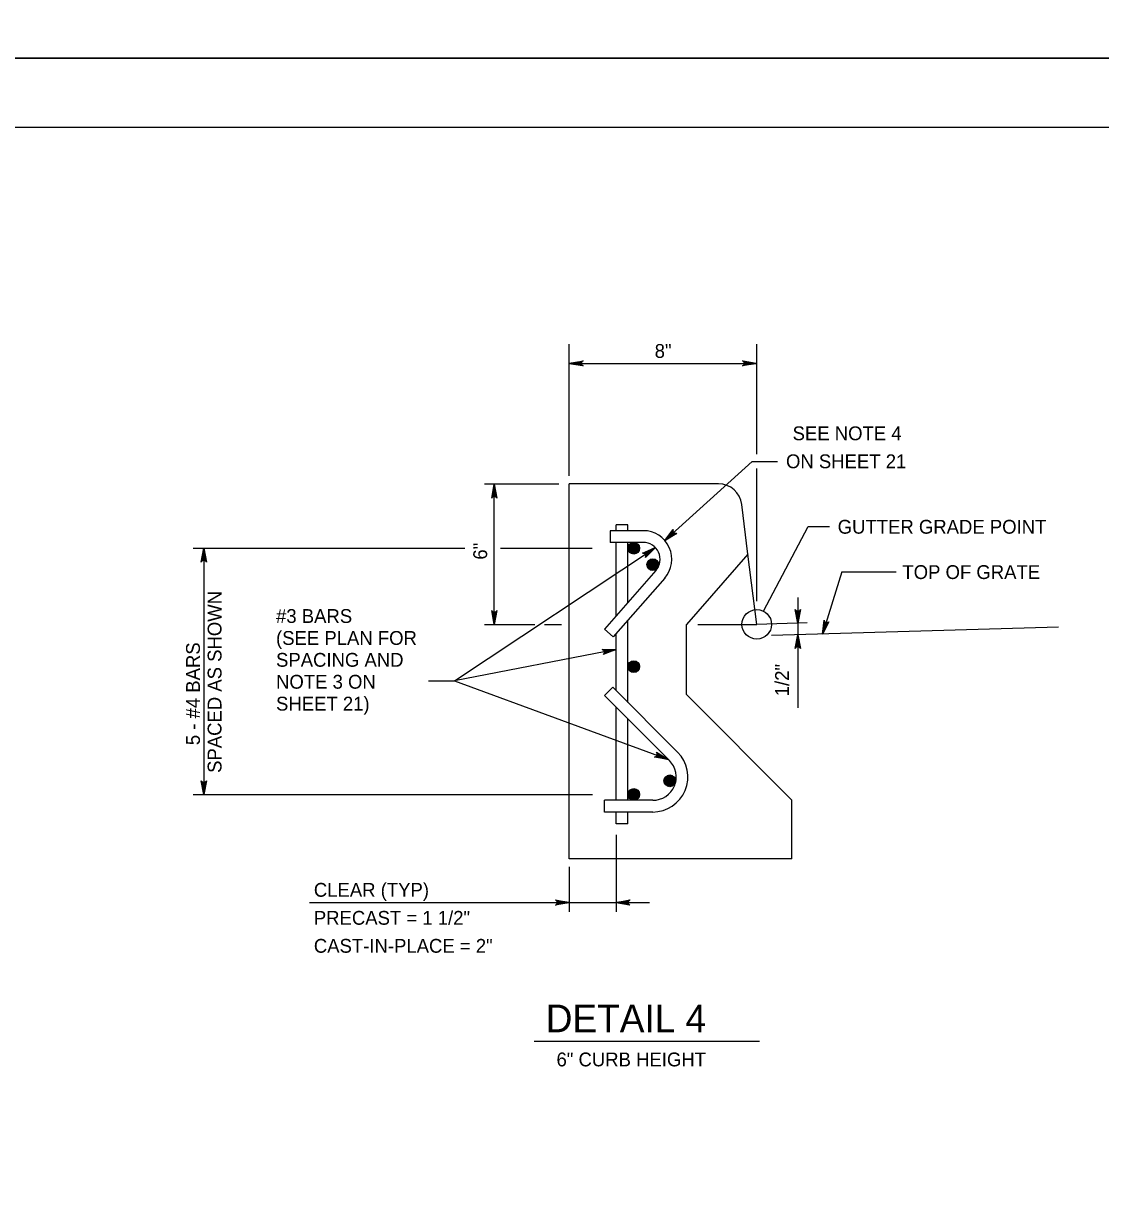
# Model space of a CAD drawing. Extents: x 2087776 to 2104538, y 970919 to 982612.
# Drawn here: x 2099759 to 2100525, y 973999 to 974842 of the extents above; entities that cross this region are included whole.
import ezdxf

# ---------------------------------------------------------------- set-up
doc = ezdxf.new("R2010")
doc.units = 0
doc.layers.add('1', color=7, linetype='Continuous')
doc.layers.add('PLT-BNDY', color=7, linetype='Continuous')

msp = doc.modelspace()

# ---------------------------------------------------------------- linework, layer by layer
at = {"layer": '1'}
for p, q in [((2100147.52, 974519.98), (2100147.52, 974613.5)), ((2100280.86, 974535.36), (2100280.86, 974613.5)), ((2100147.52, 974599.91), (2100280.86, 974599.91)), ((2100280.86, 974430.62), (2100280.86, 974525.08)), ((2100087.28, 974514.18), (2100140.19, 974514.18)), ((2100094.16, 974414.18), (2100094.16, 974514.18)), ((2100147.52, 974247.34), (2100147.52, 974514.18)), ((2100253.66, 974514.18), (2100147.52, 974514.18)), ((2100274.62, 974464.18), (2100270.19, 974499.58)), ((2100200.09, 974480.85), (2100176.68, 974480.85)), ((2100176.68, 974480.85), (2100176.68, 974472.51)), ((2100180.85, 974480.85), (2100180.85, 974485.02)), ((2100189.19, 974485.02), (2100180.85, 974485.02)), ((2100189.19, 974480.85), (2100189.19, 974485.02)), ((2100285.75, 974423.47), (2100317.46, 974483.8)), ((2100317.46, 974483.8), (2100332.63, 974483.8)), ((2099880.03, 974468.35), (2100073.14, 974468.35)), ((2099887.58, 974468.35), (2099887.58, 974293.17)), ((2100065.78, 974374.12), (2100208.76, 974468.8)), ((2100098.66, 974468.35), (2100163.89, 974468.35)), ((2100200.09, 974472.51), (2100176.68, 974472.51)), ((2100180.85, 974420.3), (2100180.85, 974472.51)), ((2100189.19, 974429.83), (2100189.19, 974472.51)), ((2100274.62, 974464.18), (2100230.86, 974414.18)), ((2100280.86, 974414.18), (2100274.62, 974464.18)), ((2100209.12, 974452.6), (2100172.51, 974410.77)), ((2100341.31, 974451.67), (2100327.57, 974407.27)), ((2100341.31, 974451.67), (2100379.96, 974451.67)), ((2100215.39, 974447.11), (2100178.79, 974405.28)), ((2100310.09, 974433.37), (2100310.09, 974354.84)), ((2100087.28, 974414.18), (2100123.1, 974414.18)), ((2100129.79, 974414.18), (2100141.9, 974414.18)), ((2100178.79, 974405.28), (2100172.51, 974410.77)), ((2100189.19, 974358.71), (2100189.19, 974417.17)), ((2100230.86, 974364.18), (2100230.86, 974414.18)), ((2100239.06, 974414.18), (2100280.86, 974414.18)), ((2100316.72, 974415.23), (2100280.86, 974414.18)), ((2100280.86, 974414.18), (2100280.86, 974414.18)), ((2100495.44, 974412.2), (2100291.4, 974406.2)), ((2100180.85, 974367.05), (2100180.85, 974407.64)), ((2100180.85, 974396.4), (2100065.78, 974374.12)), ((2100047.29, 974374.12), (2100065.78, 974374.12)), ((2100065.78, 974374.12), (2100217.99, 974318.12)), ((2100172.51, 974363.6), (2100178.41, 974369.49)), ((2100224.56, 974323.34), (2100178.41, 974369.49)), ((2100218.69, 974317.42), (2100172.51, 974363.6)), ((2100305.85, 974289.19), (2100230.86, 974364.18)), ((2100180.85, 974289), (2100180.85, 974355.26)), ((2100189.19, 974289), (2100189.19, 974346.92)), ((2099880.03, 974293.17), (2100163.93, 974293.17)), ((2100172.51, 974280.67), (2100172.51, 974289)), ((2100206.91, 974289), (2100172.51, 974289)), ((2100305.85, 974247.34), (2100305.85, 974289.19)), ((2100206.88, 974280.67), (2100172.51, 974280.67)), ((2100180.85, 974272.33), (2100180.85, 974280.67)), ((2100189.19, 974272.33), (2100189.19, 974280.67)), ((2100189.19, 974272.33), (2100180.85, 974272.33)), ((2100180.85, 974264.51), (2100180.85, 974209.72)), ((2100305.85, 974247.34), (2100147.52, 974247.34)), ((2100147.52, 974241.56), (2100147.52, 974209.72)), ((2099962.77, 974216.27), (2100204.46, 974216.27)), ((2100122.65, 974117.59), (2100282.89, 974117.59))]:
    msp.add_line(p, q, dxfattribs=at)
for points in [[(2101519.11, 972917.37), (2101519.11, 974767.76), (2098940.37, 974767.76), (2098940.37, 972917.37), (2101519.11, 972917.37), (2101519.11, 973003.85), (2100862.94, 973003.85), (2100862.94, 973216.04), (2101519.11, 973216.04), (2101519.11, 973311.07), (2100862.94, 973311.07), (2100862.94, 972917.37), (2101121.48, 972917.37), (2101121.48, 973003.85), (2101121.48, 972917.37), (2101374.1, 972917.37), (2101374.1, 973003.85), (2101374.1, 972963.44), (2101519.11, 972963.44)], [(2100147.52, 974599.91), (2100157.31, 974601.74), (2100156.93, 974601.48), (2100156.55, 974601.22), (2100156.36, 974600.89), (2100156.17, 974600.56), (2100156.11, 974600.24), (2100156.05, 974599.91), (2100156.11, 974599.58), (2100156.17, 974599.25), (2100156.36, 974598.92), (2100156.55, 974598.59), (2100156.93, 974598.33), (2100157.31, 974598.07), (2100147.52, 974599.91), (2100156.93, 974598.33), (2100156.55, 974598.59), (2100147.52, 974599.91), (2100156.36, 974598.92), (2100156.17, 974599.25), (2100147.52, 974599.91), (2100156.11, 974599.58), (2100156.05, 974599.91), (2100147.52, 974599.91), (2100156.11, 974600.24), (2100156.17, 974600.56), (2100147.52, 974599.91), (2100156.36, 974600.89), (2100156.55, 974601.22), (2100147.52, 974599.91), (2100156.93, 974601.48)], [(2100280.51, 974599.91), (2100270.72, 974598.07), (2100271.1, 974598.33), (2100271.48, 974598.59), (2100271.67, 974598.92), (2100271.87, 974599.25), (2100271.92, 974599.58), (2100271.98, 974599.91), (2100271.92, 974600.24), (2100271.87, 974600.56), (2100271.67, 974600.89), (2100271.48, 974601.22), (2100271.1, 974601.48), (2100270.72, 974601.74), (2100280.51, 974599.91), (2100271.1, 974601.48), (2100271.48, 974601.22), (2100280.51, 974599.91), (2100271.67, 974600.89), (2100271.87, 974600.56), (2100280.51, 974599.91), (2100271.92, 974600.24), (2100271.98, 974599.91), (2100280.51, 974599.91), (2100271.92, 974599.58), (2100271.87, 974599.25), (2100280.51, 974599.91), (2100271.67, 974598.92), (2100271.48, 974598.59), (2100280.51, 974599.91), (2100271.1, 974598.33)], [(2100215.51, 974473.76), (2100277.55, 974530), (2100295.65, 974530)], [(2100094.16, 974513.86), (2100096, 974504.08), (2100095.73, 974504.45), (2100095.47, 974504.83), (2100095.15, 974505.02), (2100094.82, 974505.22), (2100094.49, 974505.27), (2100094.16, 974505.33), (2100093.83, 974505.27), (2100093.5, 974505.22), (2100093.18, 974505.02), (2100092.85, 974504.83), (2100092.59, 974504.45), (2100092.33, 974504.08), (2100094.16, 974513.86), (2100092.59, 974504.45), (2100092.85, 974504.83), (2100094.16, 974513.86), (2100093.18, 974505.02), (2100093.5, 974505.22), (2100094.16, 974513.86), (2100093.83, 974505.27), (2100094.16, 974505.33), (2100094.16, 974513.86), (2100094.49, 974505.27), (2100094.82, 974505.22), (2100094.16, 974513.86), (2100095.15, 974505.02), (2100095.47, 974504.83), (2100094.16, 974513.86), (2100095.73, 974504.45)], [(2100215.51, 974473.76), (2100221.48, 974481.64), (2100221.37, 974481.2), (2100221.27, 974480.75), (2100221.35, 974480.38), (2100221.42, 974480.01), (2100221.6, 974479.73), (2100221.78, 974479.45), (2100222.04, 974479.25), (2100222.3, 974479.05), (2100222.66, 974478.94), (2100223.02, 974478.82), (2100223.47, 974478.88), (2100223.92, 974478.94), (2100215.51, 974473.76), (2100223.47, 974478.88), (2100223.02, 974478.82), (2100215.51, 974473.76), (2100222.66, 974478.94), (2100222.3, 974479.05), (2100215.51, 974473.76), (2100222.04, 974479.25), (2100221.78, 974479.45), (2100215.51, 974473.76), (2100221.6, 974479.73), (2100221.42, 974480.01), (2100215.51, 974473.76), (2100221.35, 974480.38), (2100221.27, 974480.75), (2100215.51, 974473.76), (2100221.37, 974481.2)], [(2099887.58, 974468.35), (2099889.41, 974458.56), (2099889.15, 974458.94), (2099888.89, 974459.32), (2099888.56, 974459.51), (2099888.23, 974459.7), (2099887.91, 974459.76), (2099887.58, 974459.82), (2099887.25, 974459.76), (2099886.92, 974459.7), (2099886.59, 974459.51), (2099886.27, 974459.32), (2099886.01, 974458.94), (2099885.74, 974458.56), (2099887.58, 974468.35), (2099886.01, 974458.94), (2099886.27, 974459.32), (2099887.58, 974468.35), (2099886.59, 974459.51), (2099886.92, 974459.7), (2099887.58, 974468.35), (2099887.25, 974459.76), (2099887.58, 974459.82), (2099887.58, 974468.35), (2099887.91, 974459.76), (2099888.23, 974459.7), (2099887.58, 974468.35), (2099888.56, 974459.51), (2099888.89, 974459.32), (2099887.58, 974468.35), (2099889.15, 974458.94)], [(2100208.76, 974468.8), (2100201.61, 974461.87), (2100201.78, 974462.3), (2100201.95, 974462.72), (2100201.93, 974463.11), (2100201.91, 974463.49), (2100201.78, 974463.79), (2100201.64, 974464.1), (2100201.42, 974464.34), (2100201.19, 974464.58), (2100200.84, 974464.75), (2100200.5, 974464.91), (2100200.04, 974464.92), (2100199.58, 974464.93), (2100208.76, 974468.8), (2100200.04, 974464.92), (2100200.5, 974464.91), (2100208.76, 974468.8), (2100200.84, 974464.75), (2100201.19, 974464.58), (2100208.76, 974468.8), (2100201.42, 974464.34), (2100201.64, 974464.1), (2100208.76, 974468.8), (2100201.78, 974463.79), (2100201.91, 974463.49), (2100208.76, 974468.8), (2100201.93, 974463.11), (2100201.95, 974462.72), (2100208.76, 974468.8), (2100201.78, 974462.3)], [(2100094.16, 974414.18), (2100092.33, 974423.96), (2100092.59, 974423.58), (2100092.85, 974423.21), (2100093.18, 974423.01), (2100093.5, 974422.82), (2100093.83, 974422.76), (2100094.16, 974422.71), (2100094.49, 974422.76), (2100094.82, 974422.82), (2100095.15, 974423.01), (2100095.47, 974423.21), (2100095.73, 974423.58), (2100096, 974423.96), (2100094.16, 974414.18), (2100095.73, 974423.58), (2100095.47, 974423.21), (2100094.16, 974414.18), (2100095.15, 974423.01), (2100094.82, 974422.82), (2100094.16, 974414.18), (2100094.49, 974422.76), (2100094.16, 974422.71), (2100094.16, 974414.18), (2100093.83, 974422.76), (2100093.5, 974422.82), (2100094.16, 974414.18), (2100093.18, 974423.01), (2100092.85, 974423.21), (2100094.16, 974414.18), (2100092.59, 974423.58)], [(2100310.09, 974415.03), (2100308.25, 974424.82), (2100308.51, 974424.44), (2100308.77, 974424.07), (2100309.1, 974423.87), (2100309.43, 974423.68), (2100309.76, 974423.62), (2100310.09, 974423.56), (2100310.42, 974423.62), (2100310.74, 974423.68), (2100311.07, 974423.87), (2100311.4, 974424.07), (2100311.66, 974424.44), (2100311.92, 974424.82), (2100310.09, 974415.03), (2100311.66, 974424.44), (2100311.4, 974424.07), (2100310.09, 974415.03), (2100311.07, 974423.87), (2100310.74, 974423.68), (2100310.09, 974415.03), (2100310.42, 974423.62), (2100310.09, 974423.56), (2100310.09, 974415.03), (2100309.76, 974423.62), (2100309.43, 974423.68), (2100310.09, 974415.03), (2100309.1, 974423.87), (2100308.77, 974424.07), (2100310.09, 974415.03), (2100308.51, 974424.44)], [(2100327.57, 974407.27), (2100328.71, 974417.16), (2100328.85, 974416.72), (2100328.99, 974416.28), (2100329.24, 974416), (2100329.5, 974415.72), (2100329.79, 974415.57), (2100330.09, 974415.42), (2100330.42, 974415.37), (2100330.75, 974415.33), (2100331.12, 974415.42), (2100331.49, 974415.51), (2100331.85, 974415.79), (2100332.21, 974416.07), (2100327.57, 974407.27), (2100331.85, 974415.79), (2100331.49, 974415.51), (2100327.57, 974407.27), (2100331.12, 974415.42), (2100330.75, 974415.33), (2100327.57, 974407.27), (2100330.42, 974415.37), (2100330.09, 974415.42), (2100327.57, 974407.27), (2100329.79, 974415.57), (2100329.5, 974415.72), (2100327.57, 974407.27), (2100329.24, 974416), (2100328.99, 974416.28), (2100327.57, 974407.27), (2100328.85, 974416.72)], [(2100310.09, 974406.75), (2100311.92, 974396.97), (2100311.66, 974397.34), (2100311.4, 974397.72), (2100311.07, 974397.92), (2100310.74, 974398.11), (2100310.42, 974398.17), (2100310.09, 974398.22), (2100309.76, 974398.17), (2100309.43, 974398.11), (2100309.1, 974397.92), (2100308.77, 974397.72), (2100308.51, 974397.34), (2100308.25, 974396.97), (2100310.09, 974406.75), (2100308.51, 974397.34), (2100308.77, 974397.72), (2100310.09, 974406.75), (2100309.1, 974397.92), (2100309.43, 974398.11), (2100310.09, 974406.75), (2100309.76, 974398.17), (2100310.09, 974398.22), (2100310.09, 974406.75), (2100310.42, 974398.17), (2100310.74, 974398.11), (2100310.09, 974406.75), (2100311.07, 974397.92), (2100311.4, 974397.72), (2100310.09, 974406.75), (2100311.66, 974397.34)], [(2100180.85, 974396.4), (2100171.6, 974392.74), (2100171.92, 974393.07), (2100172.24, 974393.4), (2100172.36, 974393.76), (2100172.49, 974394.12), (2100172.49, 974394.45), (2100172.48, 974394.78), (2100172.36, 974395.09), (2100172.24, 974395.4), (2100171.99, 974395.69), (2100171.74, 974395.97), (2100171.32, 974396.16), (2100170.9, 974396.34), (2100180.85, 974396.4), (2100171.32, 974396.16), (2100171.74, 974395.97), (2100180.85, 974396.4), (2100171.99, 974395.69), (2100172.24, 974395.4), (2100180.85, 974396.4), (2100172.36, 974395.09), (2100172.48, 974394.78), (2100180.85, 974396.4), (2100172.49, 974394.45), (2100172.49, 974394.12), (2100180.85, 974396.4), (2100172.36, 974393.76), (2100172.24, 974393.4), (2100180.85, 974396.4), (2100171.92, 974393.07)], [(2100217.99, 974318.12), (2100208.18, 974319.77), (2100208.62, 974319.89), (2100209.06, 974320), (2100209.36, 974320.24), (2100209.65, 974320.48), (2100209.82, 974320.77), (2100209.99, 974321.06), (2100210.05, 974321.39), (2100210.11, 974321.72), (2100210.04, 974322.09), (2100209.97, 974322.47), (2100209.71, 974322.84), (2100209.44, 974323.22), (2100217.99, 974318.12), (2100209.71, 974322.84), (2100209.97, 974322.47), (2100217.99, 974318.12), (2100210.04, 974322.09), (2100210.11, 974321.72), (2100217.99, 974318.12), (2100210.05, 974321.39), (2100209.99, 974321.06), (2100217.99, 974318.12), (2100209.82, 974320.77), (2100209.65, 974320.48), (2100217.99, 974318.12), (2100209.36, 974320.24), (2100209.06, 974320), (2100217.99, 974318.12), (2100208.62, 974319.89)], [(2099887.58, 974293.17), (2099885.74, 974302.95), (2099886.01, 974302.58), (2099886.27, 974302.2), (2099886.59, 974302), (2099886.92, 974301.81), (2099887.25, 974301.75), (2099887.58, 974301.7), (2099887.91, 974301.75), (2099888.23, 974301.81), (2099888.56, 974302), (2099888.89, 974302.2), (2099889.15, 974302.58), (2099889.41, 974302.95), (2099887.58, 974293.17), (2099889.15, 974302.58), (2099888.89, 974302.2), (2099887.58, 974293.17), (2099888.56, 974302), (2099888.23, 974301.81), (2099887.58, 974293.17), (2099887.91, 974301.75), (2099887.58, 974301.7), (2099887.58, 974293.17), (2099887.25, 974301.75), (2099886.92, 974301.81), (2099887.58, 974293.17), (2099886.59, 974302), (2099886.27, 974302.2), (2099887.58, 974293.17), (2099886.01, 974302.58)], [(2100147.52, 974216.27), (2100137.74, 974214.44), (2100138.11, 974214.7), (2100138.49, 974214.96), (2100138.69, 974215.29), (2100138.88, 974215.61), (2100138.94, 974215.94), (2100138.99, 974216.27), (2100138.94, 974216.6), (2100138.88, 974216.93), (2100138.69, 974217.25), (2100138.49, 974217.58), (2100138.11, 974217.84), (2100137.74, 974218.1), (2100147.52, 974216.27), (2100138.11, 974217.84), (2100138.49, 974217.58), (2100147.52, 974216.27), (2100138.69, 974217.25), (2100138.88, 974216.93), (2100147.52, 974216.27), (2100138.94, 974216.6), (2100138.99, 974216.27), (2100147.52, 974216.27), (2100138.94, 974215.94), (2100138.88, 974215.61), (2100147.52, 974216.27), (2100138.69, 974215.29), (2100138.49, 974214.96), (2100147.52, 974216.27), (2100138.11, 974214.7)], [(2100180.85, 974216.27), (2100190.64, 974218.1), (2100190.26, 974217.84), (2100189.88, 974217.58), (2100189.69, 974217.25), (2100189.5, 974216.93), (2100189.44, 974216.6), (2100189.38, 974216.27), (2100189.44, 974215.94), (2100189.5, 974215.61), (2100189.69, 974215.29), (2100189.88, 974214.96), (2100190.26, 974214.7), (2100190.64, 974214.44), (2100180.85, 974216.27), (2100190.26, 974214.7), (2100189.88, 974214.96), (2100180.85, 974216.27), (2100189.69, 974215.29), (2100189.5, 974215.61), (2100180.85, 974216.27), (2100189.44, 974215.94), (2100189.38, 974216.27), (2100180.85, 974216.27), (2100189.44, 974216.6), (2100189.5, 974216.93), (2100180.85, 974216.27), (2100189.69, 974217.25), (2100189.88, 974217.58), (2100180.85, 974216.27), (2100190.26, 974217.84)]]:
    msp.add_lwpolyline(points, dxfattribs=at)
for centre, radius in [((2100193.4, 974468.35), 4.17), ((2100193.4, 974468.35), 3.87), ((2100193.4, 974468.35), 3.58), ((2100193.4, 974468.35), 3.28), ((2100193.4, 974468.35), 2.98), ((2100193.4, 974468.35), 2.69), ((2100193.4, 974468.35), 2.39), ((2100193.4, 974468.35), 2.1), ((2100193.4, 974468.35), 1.8), ((2100193.4, 974468.35), 1.5), ((2100193.4, 974468.35), 1.21), ((2100193.4, 974468.35), 0.912), ((2100193.4, 974468.35), 0.616), ((2100193.4, 974468.35), 0.32), ((2100206.95, 974456.68), 4.17), ((2100206.95, 974456.68), 3.87), ((2100206.95, 974456.68), 3.58), ((2100206.95, 974456.68), 3.28), ((2100206.95, 974456.68), 2.98), ((2100206.95, 974456.68), 2.69), ((2100206.95, 974456.68), 2.39), ((2100206.95, 974456.68), 2.1), ((2100206.95, 974456.68), 1.8), ((2100206.95, 974456.68), 1.5), ((2100206.95, 974456.68), 1.21), ((2100206.95, 974456.68), 0.912), ((2100206.95, 974456.68), 0.616), ((2100206.95, 974456.68), 0.32), ((2100280.86, 974414.18), 10.5), ((2100193.4, 974384.14), 4.17), ((2100193.4, 974384.14), 3.87), ((2100193.4, 974384.14), 3.58), ((2100193.4, 974384.14), 3.28), ((2100193.4, 974384.14), 2.98), ((2100193.4, 974384.14), 2.69), ((2100193.4, 974384.14), 2.39), ((2100193.4, 974384.14), 2.1), ((2100193.4, 974384.14), 1.8), ((2100193.4, 974384.14), 1.5), ((2100193.4, 974384.14), 1.21), ((2100193.4, 974384.14), 0.912), ((2100193.4, 974384.14), 0.616), ((2100193.4, 974384.14), 0.32), ((2100219.05, 974302.86), 4.17), ((2100219.05, 974302.86), 3.87), ((2100219.05, 974302.86), 3.58), ((2100219.05, 974302.86), 3.28), ((2100219.05, 974302.86), 2.98), ((2100219.05, 974302.86), 2.69), ((2100219.05, 974302.86), 2.39), ((2100219.05, 974302.86), 2.1), ((2100219.05, 974302.86), 1.8), ((2100219.05, 974302.86), 1.5), ((2100219.05, 974302.86), 1.21), ((2100219.05, 974302.86), 0.912), ((2100219.05, 974302.86), 0.616), ((2100219.05, 974302.86), 0.32), ((2100193.4, 974293.17), 4.17), ((2100193.4, 974293.17), 3.87), ((2100193.4, 974293.17), 3.58), ((2100193.4, 974293.17), 3.28), ((2100193.4, 974293.17), 2.98), ((2100193.4, 974293.17), 2.69), ((2100193.4, 974293.17), 2.39), ((2100193.4, 974293.17), 2.1), ((2100193.4, 974293.17), 1.8), ((2100193.4, 974293.17), 1.5), ((2100193.4, 974293.17), 1.21), ((2100193.4, 974293.17), 0.912), ((2100193.4, 974293.17), 0.616), ((2100193.4, 974293.17), 0.32)]:
    msp.add_circle(centre, radius, dxfattribs=at)
for centre, radius, start, end in [((2100253.66, 974497.51), 16.67, 7.12184, 90), ((2100200.09, 974460.51), 20.34, 318.81225, 90), ((2100200.09, 974460.51), 12, 318.81225, 90), ((2100206.88, 974305.67), 25, 270, 45), ((2100206.91, 974305.65), 16.65, 270, 45)]:
    msp.add_arc(centre, radius, start, end, dxfattribs=at)
at = {"layer": 'PLT-BNDY'}
for points in [[(2098812.42, 976765.79), (2101571.61, 976765.79), (2101571.61, 974816.97), (2098812.42, 974816.97)], [(2098812.42, 974816.97), (2101571.61, 974816.97), (2101571.61, 972868.16), (2098812.42, 972868.16)]]:
    msp.add_lwpolyline(points, close=True, dxfattribs=at)

# ---------------------------------------------------------------- texts
at = {"layer": '1'}
for s, height, p in [('8"', 9.843, (2100208.26, 974603.8)), ('SEE NOTE 4', 9.843, (2100306.36, 974545.21)), ('ON SHEET 21', 9.8425, (2100301.67, 974525.29)), ('GUTTER GRADE POINT', 9.8425, (2100338.42, 974478.7)), ('TOP OF GRATE', 9.8425, (2100384.44, 974446.46)), ('#3 BARS', 9.843, (2099938.93, 974415.19)), ('(SEE PLAN FOR', 9.8425, (2099938.93, 974399.6)), ('SPACING AND', 9.8425, (2099938.93, 974384.02)), ('NOTE 3 ON', 9.843, (2099938.93, 974368.43)), ('SHEET 21)', 9.843, (2099938.93, 974352.85)), ('CLEAR (TYP)', 9.8425, (2099965.83, 974220.38)), ('PRECAST = 1 1/2"', 9.8425, (2099965.83, 974200.46)), ('CAST-IN-PLACE = 2"', 9.8425, (2099965.83, 974180.54)), ('DETAIL 4', 19.685, (2100130.76, 974123.99)), ('6" CURB HEIGHT', 9.8425, (2100138.43, 974099.71))]:
    msp.add_text(s, height=height, dxfattribs=at).set_placement(p)
for s, height, p in [('6"', 9.843, (2100089.08, 974460.25)), ('SPACED AS SHOWN', 9.8425, (2099900.14, 974308.51)), ('5 - #4 BARS', 9.8425, (2099884.78, 974328.24)), ('1/2"', 9.843, (2100303.79, 974363.05))]:
    msp.add_text(s, height=height, rotation=90, dxfattribs=at).set_placement(p)

doc.saveas('drawing.dxf')
